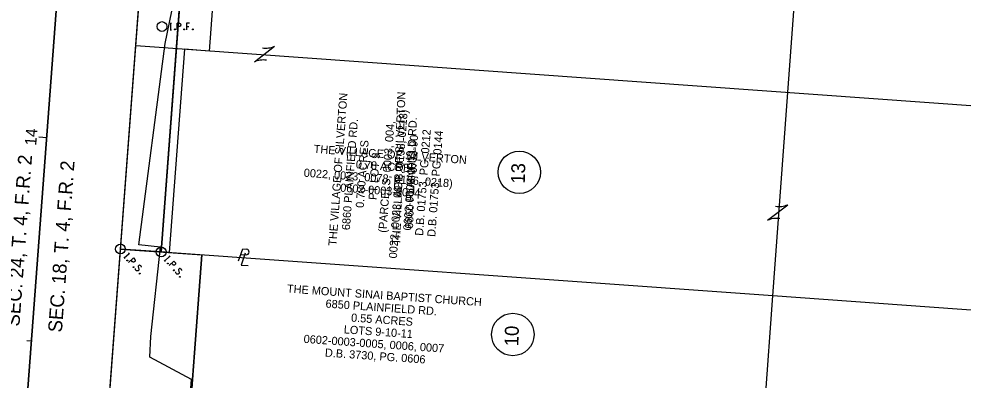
# Model space of a CAD drawing. Extents: x 204354 to 231038, y 361459 to 365260.
# Drawn here: x 220550.5 to 220781.9, y 361901.8 to 361990.4 of the extents above; entities that cross this region are included whole.
import ezdxf

# ---------------------------------------------------------------- set-up
doc = ezdxf.new("R2010")
doc.units = 0
for name, color, linetype in [('CM_Corridor_Point_Control', 7, 'Continuous'), ('CM_Corridor_Range_Conceptual', 7, 'Continuous'), ('DT_P_Contour_Minor', 7, 'Continuous'), ('DT_P_Contour_Text', 7, 'Continuous'), ('DT_P_Triangles', 7, 'Continuous'), ('DT_X_Contour_Minor', 7, 'Continuous'), ('MD_P_CURB_BACK_BOT', 7, 'Continuous'), ('MD_P_Intersection_MatchLine', 7, 'Continuous'), ('MD_P_Surface_Finished_Grade', 7, 'Continuous'), ('MD_P_SW_BOT', 7, 'Continuous'), ('MD_P_SW_TOP', 7, 'Continuous'), ('PV_P_Saw_Cut_Line', 7, 'Continuous'), ('PV_P_Walk', 7, 'Continuous'), ('SC_Scratch10', 7, 'Continuous'), ('SC_Shading1', 7, 'Continuous'), ('SC_Shading2', 7, 'Continuous'), ('SH_Text', 7, 'Continuous')]:
    doc.layers.add(name, color=color, linetype=linetype)

msp = doc.modelspace()

# ---------------------------------------------------------------- linework, layer by layer
at = {"layer": 'CM_Corridor_Range_Conceptual'}
msp.add_line((220527.43, 361562.35), (220572.38, 362161.22), dxfattribs=at)
msp.add_line((220527.43, 361562.35), (220572.38, 362161.22), dxfattribs=at)
at = {"layer": 'DT_P_Contour_Text'}
for centre in [(220673.12, 361952.78), (220671.54, 361912.98)]:
    msp.add_circle(centre, 5.2, dxfattribs=at)
at = {"layer": 'DT_P_Triangles'}
msp.add_lwpolyline([(220591.41, 361883.96), (220592.81, 361901.94), (220582.59, 361907.43), (220582.82, 361912.47), (220585.15, 361934.4), (220579.89, 361934.96), (220586.33, 361984.39), (220590.86, 362006.25), (220598.44, 362006.06), (220600.6, 362036.54), (220594.76, 362038.06), (220598.79, 362090.98), (220600.58, 362106.63), (220627.44, 362136.57), (220681.45, 362145.38), (220690.29, 362141.5), (220716, 362145.59)], dxfattribs=at)
at = {"layer": 'MD_P_CURB_BACK_BOT'}
for p, q in [((220557.37, 361961.23), (220555.38, 361961.38)), ((220553.63, 361911.37), (220552.43, 361911.46))]:
    msp.add_line(p, q, dxfattribs=at)
at = {"layer": 'MD_P_Intersection_MatchLine'}
for p, q in [((220575.38, 361933.94), (220587.35, 361933.1)), ((220575.57, 361933.92), (220595.33, 361932.5)), ((220584.1, 361782.9), (220595.33, 361932.5)), ((220584.1, 361782.92), (220595.33, 361932.5))]:
    msp.add_line(p, q, dxfattribs=at)
at = {"layer": 'MD_P_Surface_Finished_Grade'}
for points in [[(220587.56, 361989.32), (220587.92, 361989.32)], [(220587.74, 361987.72), (220587.74, 361989.32)], [(220589.31, 361987.72), (220589.31, 361989.32), (220589.84, 361989.32), (220589.89, 361989.3), (220589.97, 361989.28), (220590, 361989.25), (220590.03, 361989.23), (220590.08, 361989.17), (220590.11, 361989.1), (220590.13, 361989), (220590.13, 361988.85), (220590.12, 361988.8), (220590.1, 361988.72), (220590.06, 361988.64), (220590.01, 361988.6), (220589.98, 361988.57), (220589.92, 361988.55), (220589.84, 361988.54), (220589.31, 361988.54)], [(220592.32, 361989.32), (220591.55, 361989.32), (220591.55, 361987.72)], [(220591.55, 361988.54), (220592.09, 361988.54)], [(220587.56, 361987.72), (220587.92, 361987.72)], [(220588.7, 361987.93), (220588.75, 361987.93), (220588.79, 361987.91), (220588.82, 361987.86), (220588.82, 361987.79), (220588.79, 361987.74), (220588.75, 361987.72), (220588.7, 361987.72), (220588.67, 361987.74), (220588.63, 361987.79), (220588.63, 361987.86), (220588.67, 361987.91), (220588.7, 361987.93)], [(220590.95, 361987.93), (220591, 361987.93), (220591.04, 361987.91), (220591.07, 361987.86), (220591.07, 361987.79), (220591.04, 361987.74), (220591, 361987.72), (220590.95, 361987.72), (220590.92, 361987.74), (220590.88, 361987.79), (220590.88, 361987.86), (220590.92, 361987.91), (220590.95, 361987.93)], [(220593.1, 361987.93), (220593.15, 361987.93), (220593.19, 361987.91), (220593.22, 361987.86), (220593.22, 361987.79), (220593.19, 361987.74), (220593.15, 361987.72), (220593.1, 361987.72), (220593.06, 361987.74), (220593.03, 361987.79), (220593.03, 361987.86), (220593.06, 361987.91), (220593.1, 361987.93)]]:
    msp.add_lwpolyline(points, dxfattribs=at)
msp.add_circle((220585.55, 361988.52), 1.2, dxfattribs=at)
at = {"layer": 'MD_P_SW_BOT'}
for p, q in [((220743.2, 362031.54), (220735.16, 361922.46)), ((220898.55, 361960.84), (220579.12, 361983.8)), ((220608.19, 361979.86), (220613.13, 361983.68)), ((220610.66, 361981.77), (220610.66, 361981.77)), ((220733.96, 361941), (220738.9, 361944.82)), ((220736.43, 361942.91), (220736.43, 361942.91)), ((220735.27, 361922.44), (220575.38, 361933.94)), ((220604.86, 361932.64), (220606.16, 361932.55)), ((220605.62, 361931.96), (220605.62, 361931.96)), ((220735.16, 361922.45), (220731.49, 361872.59)), ((220894.66, 361910.99), (220735.27, 361922.44))]:
    msp.add_line(p, q, dxfattribs=at)
for points in [[(220604.33, 361931.09), (220605.33, 361933.99), (220606.36, 361933.91)], [(220605.95, 361932.9), (220604.94, 361930.01), (220606.69, 361929.88)]]:
    msp.add_lwpolyline(points, dxfattribs=at)
for centre, radius, start, end in [((220610.98, 361988.56), 5.34, 261.2021, 293.8446), ((220610.35, 361974.98), 5.34, 81.2021, 113.8446), ((220736.74, 361949.7), 5.34, 261.2021, 293.8446), ((220736.11, 361936.12), 5.34, 81.2021, 113.8446), ((220606.2, 361933.24), 0.69, 266.2039, 77.061)]:
    msp.add_arc(centre, radius, start, end, dxfattribs=at)
at = {"layer": 'MD_P_SW_TOP'}
msp.add_line((220519.7, 361460.36), (220580.15, 362265.73), dxfattribs=at)
at = {"layer": 'PV_P_Saw_Cut_Line'}
msp.add_line((220585.36, 361933.24), (220598.42, 362107.33), dxfattribs=at)
at = {"layer": 'PV_P_Walk'}
msp.add_line((220549.24, 361585.75), (220590.37, 362133.66), dxfattribs=at)
msp.add_line((220549.24, 361585.75), (220590.37, 362133.66), dxfattribs=at)
at = {"layer": 'SC_Scratch10'}
for p, q in [((220585.35, 361933.22), (220600.34, 362132.91)), ((220585.36, 361933.24), (220575.38, 361933.94))]:
    msp.add_line(p, q, dxfattribs=at)
at = {"layer": 'SC_Shading1'}
for points in [[(220575.38, 361933.94), (220583.57, 362043.09), (220593.55, 362042.37), (220585.35, 361933.22)], [(220585.35, 361933.22), (220593.55, 362042.37), (220601.53, 362041.8), (220597.08, 361982.5), (220591.09, 361982.93), (220587.35, 361933.07)], [(220564.15, 361784.36), (220575.38, 361933.94), (220595.33, 361932.5), (220584.1, 361782.92)]]:
    msp.add_lwpolyline(points, close=True, dxfattribs=at)
at = {"layer": 'SC_Shading2'}
for points in [[(220576.3, 361931.79), (220577.47, 361932.89)], [(220577.35, 361933.01), (220577.59, 361932.76)], [(220576.18, 361931.92), (220576.42, 361931.66)], [(220577.12, 361931.24), (220577.15, 361931.2), (220577.16, 361931.16), (220577.14, 361931.1), (220577.1, 361931.05), (220577.04, 361931.04), (220577, 361931.05), (220576.96, 361931.09), (220576.96, 361931.13), (220576.97, 361931.19), (220577.02, 361931.23), (220577.07, 361931.24), (220577.12, 361931.24)], [(220577.37, 361930.65), (220578.54, 361931.75), (220578.9, 361931.36), (220578.93, 361931.31), (220578.97, 361931.24), (220578.97, 361931.2), (220578.97, 361931.16), (220578.96, 361931.08), (220578.94, 361931.01), (220578.88, 361930.93), (220578.77, 361930.82), (220578.72, 361930.8), (220578.65, 361930.76), (220578.56, 361930.73), (220578.5, 361930.74), (220578.46, 361930.75), (220578.4, 361930.77), (220578.33, 361930.83), (220577.97, 361931.21)], [(220586.12, 361931.19), (220586.35, 361930.92)], [(220586.24, 361931.06), (220587.42, 361932.13)], [(220587.29, 361929.9), (220588.47, 361930.97), (220588.83, 361930.58), (220588.86, 361930.53), (220588.89, 361930.45), (220588.89, 361930.41), (220588.9, 361930.37), (220588.88, 361930.3), (220588.85, 361930.23), (220588.79, 361930.15), (220588.68, 361930.04), (220588.64, 361930.02), (220588.57, 361929.98), (220588.47, 361929.96), (220588.41, 361929.97), (220588.37, 361929.97), (220588.32, 361930), (220588.25, 361930.05), (220587.89, 361930.45)], [(220587.3, 361932.26), (220587.54, 361932)], [(220578.66, 361929.6), (220578.69, 361929.56), (220578.7, 361929.52), (220578.68, 361929.46), (220578.64, 361929.42), (220578.58, 361929.41), (220578.54, 361929.41), (220578.5, 361929.45), (220578.5, 361929.49), (220578.51, 361929.55), (220578.56, 361929.6), (220578.62, 361929.61), (220578.66, 361929.6)], [(220580.52, 361929.48), (220580.52, 361929.51), (220580.52, 361929.55), (220580.48, 361929.65), (220580.41, 361929.75), (220580.35, 361929.82), (220580.33, 361929.84), (220580.2, 361929.92), (220580.07, 361929.96), (220579.94, 361929.95), (220579.85, 361929.89), (220579.8, 361929.84), (220579.74, 361929.76), (220579.73, 361929.63), (220579.88, 361928.93), (220579.88, 361928.86), (220579.85, 361928.8), (220579.81, 361928.74), (220579.76, 361928.69), (220579.7, 361928.64), (220579.65, 361928.61), (220579.59, 361928.59), (220579.54, 361928.57), (220579.5, 361928.56), (220579.45, 361928.56), (220579.41, 361928.56), (220579.36, 361928.58), (220579.33, 361928.59), (220579.25, 361928.66), (220579.14, 361928.77), (220579.09, 361928.86), (220579.06, 361929.03), (220579.05, 361929.14)], [(220587.04, 361930.49), (220587.08, 361930.45), (220587.08, 361930.41), (220587.06, 361930.35), (220587.02, 361930.31), (220586.96, 361930.3), (220586.92, 361930.3), (220586.88, 361930.34), (220586.88, 361930.39), (220586.89, 361930.44), (220586.94, 361930.49), (220587, 361930.5), (220587.04, 361930.49)], [(220588.55, 361928.82), (220588.59, 361928.78), (220588.59, 361928.74), (220588.57, 361928.68), (220588.53, 361928.64), (220588.47, 361928.63), (220588.43, 361928.64), (220588.39, 361928.68), (220588.39, 361928.72), (220588.4, 361928.78), (220588.45, 361928.82), (220588.51, 361928.83), (220588.55, 361928.82)], [(220590.41, 361928.66), (220590.41, 361928.7), (220590.41, 361928.74), (220590.37, 361928.84), (220590.31, 361928.94), (220590.25, 361929.01), (220590.23, 361929.03), (220590.1, 361929.12), (220589.97, 361929.15), (220589.84, 361929.14), (220589.75, 361929.09), (220589.69, 361929.04), (220589.63, 361928.96), (220589.63, 361928.83), (220589.76, 361928.13), (220589.75, 361928.06), (220589.73, 361928.01), (220589.69, 361927.94), (220589.64, 361927.89), (220589.57, 361927.84), (220589.53, 361927.82), (220589.47, 361927.79), (220589.41, 361927.78), (220589.37, 361927.77), (220589.32, 361927.77), (220589.28, 361927.77), (220589.23, 361927.79), (220589.2, 361927.81), (220589.12, 361927.87), (220589.02, 361927.98), (220588.97, 361928.07), (220588.94, 361928.24), (220588.94, 361928.36)], [(220580.15, 361928.01), (220580.19, 361927.97), (220580.19, 361927.93), (220580.18, 361927.87), (220580.13, 361927.83), (220580.08, 361927.82), (220580.03, 361927.82), (220580, 361927.86), (220579.99, 361927.9), (220580.01, 361927.96), (220580.05, 361928.01), (220580.11, 361928.02), (220580.15, 361928.01)], [(220590.02, 361927.21), (220590.05, 361927.16), (220590.06, 361927.12), (220590.04, 361927.07), (220589.99, 361927.02), (220589.93, 361927.01), (220589.89, 361927.02), (220589.86, 361927.06), (220589.85, 361927.1), (220589.87, 361927.16), (220589.91, 361927.2), (220589.97, 361927.21), (220590.02, 361927.21)]]:
    msp.add_lwpolyline(points, dxfattribs=at)
for centre in [(220575.38, 361933.94), (220585.35, 361933.22)]:
    msp.add_circle(centre, 1.2, dxfattribs=at)
at = {"layer": 'SH_Text'}
for p, q in [((220575.38, 361933.94), (220583.57, 362043.09)), ((220593.55, 362042.37), (220585.35, 361933.22)), ((220585.35, 361933.22), (220575.38, 361933.94))]:
    msp.add_line(p, q, dxfattribs=at)

# ---------------------------------------------------------------- texts
at = {"layer": 'CM_Corridor_Point_Control'}
for s, p in [('THE VILLAGE OF SILVERTON', (220643.92, 361934.93)), ('6860 PLAINFIELD RD.', (220647.06, 361938.9))]:
    msp.add_text(s, height=2, rotation=88, dxfattribs=at).set_placement(p)
at = {"layer": 'DT_P_Contour_Minor'}
for s, height, rotation, p in [('THE VILLAGE OF SILVERTON', 2, 85.8353, (220628.3, 361934.68)), ('0022, 0023, 0078, 0196, 0218)', 2, 85.8353, (220643.11, 361931.59)), ('6860 PLAINFIELD RD.', 2, 85.8353, (220631.59, 361938.53)), ('(PARCELS, 0003, 004,', 2, 85.8353, (220640.56, 361937.89)), ('D.B. 01753, PG. 0212', 2, 85.8353, (220649.53, 361937.14)), (' 0602-0003-0003-90', 2, 85.8353, (220646.57, 361937.72)), ('D.B. 01753, PG. 0144', 2, 85.8353, (220652.52, 361936.87)), (' 0.780 ACRES ', 2, 85.8353, (220634.94, 361943.24)), ('SEC. 24, T. 4, F.R. 2', 3.4, 85.7455, (220550.6, 361914.87)), ('PT LOT 9', 2, 85.8353, (220638.14, 361945.93)), ('SEC. 18, T. 4, F.R. 2', 3.4, 85.7455, (220561.01, 361913.41)), ('THE MOUNT SINAI BAPTIST CHURCH', 2, 356, (220616.13, 361923.27)), ('6850 PLAINFIELD RD.', 2, 356, (220625.58, 361919.6)), (' 0.55 ACRES', 2, 356, (220631.1, 361916.21)), ('LOTS 9-10-11', 2, 356, (220630.05, 361913.27)), (' 0602-0003-0005, 0006, 0007', 2, 356, (220619.47, 361911)), ('D.B. 3730, PG. 0606', 2, 356, (220625.43, 361907.58))]:
    msp.add_text(s, height=height, rotation=rotation, dxfattribs=at).set_placement(p)
at = {"layer": 'DT_P_Contour_Text'}
for s, p in [('13', (220674.45, 361949.92)), ('10', (220672.87, 361910.04))]:
    msp.add_text(s, height=3.4, rotation=88.3143, dxfattribs=at).set_placement(p)
at = {"layer": 'DT_X_Contour_Minor'}
for s, p in [('THE VILLAGE OF SILVERTON', (220622.68, 361957.53)), (' 0.78 ACRES ', (220632.25, 361953.83)), ('0022, 0023, 0078, 0196, 0218)', (220620.24, 361951.7)), (' 0602-0003-0004', (220628.43, 361948.09))]:
    msp.add_text(s, height=2, rotation=355.8353, dxfattribs=at).set_placement(p)
at = {"layer": 'MD_P_CURB_BACK_BOT'}
msp.add_text('14', height=2.8, rotation=85.7073, dxfattribs=at).set_placement((220554.72, 361959.26))

doc.saveas('drawing.dxf')
